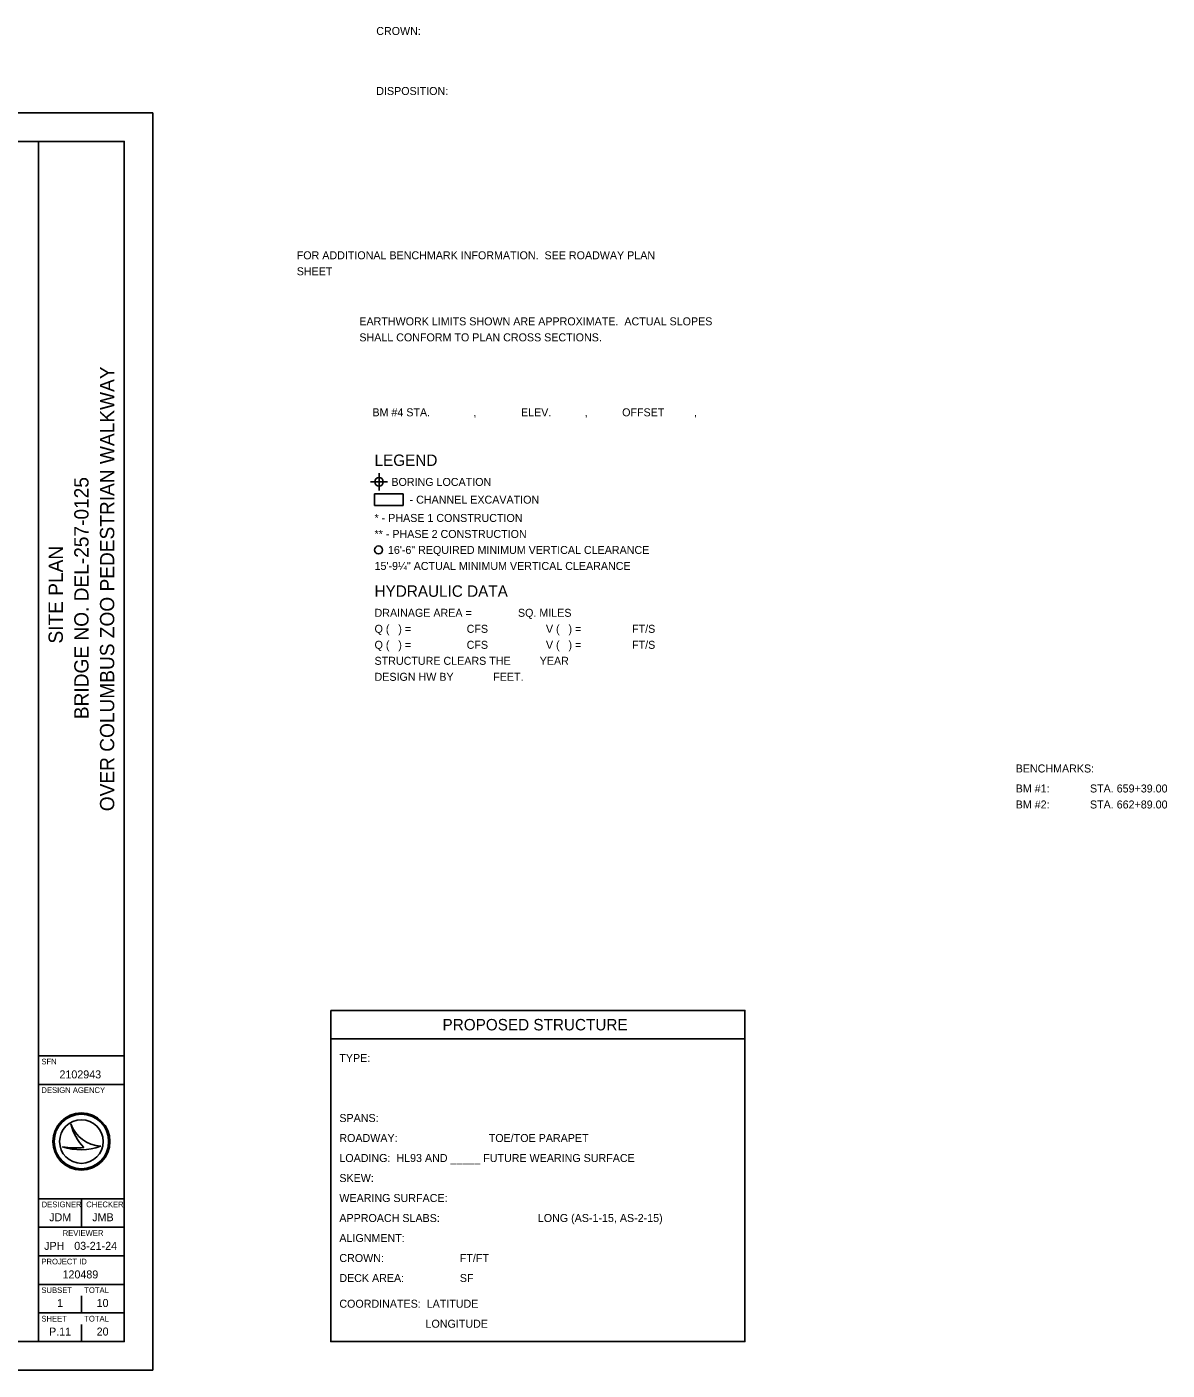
# Model space of a CAD drawing. Extents: x -8 to 51.8, y 0 to 37.2.
# Drawn here: x 31.8 to 51.75, y 0 to 23.51 of the extents above; entities that cross this region are included whole.
import ezdxf

# ---------------------------------------------------------------- set-up
doc = ezdxf.new("R2010")
doc.units = 0
for name, color, linetype in [('GT_Project_Soil_Boring', 7, 'Continuous'), ('SH_Border', 7, 'Continuous'), ('SH_Cut_Line', 7, 'Continuous'), ('SH_Data', 7, 'Continuous')]:
    doc.layers.add(name, color=color, linetype=linetype)

msp = doc.modelspace()

# ---------------------------------------------------------------- linework, layer by layer
at = {"layer": 'GT_Project_Soil_Boring'}
for p, q in [((37.959, 15.543), (37.809, 15.543)), ((37.959, 15.543), (37.884, 15.543)), ((37.959, 15.543), (37.959, 15.693)), ((37.959, 15.618), (37.959, 15.543)), ((37.959, 15.543), (37.959, 15.393)), ((37.959, 15.543), (38.109, 15.543)), ((37.959, 15.468), (37.959, 15.543)), ((37.959, 15.543), (38.034, 15.543))]:
    msp.add_line(p, q, dxfattribs=at)
msp.add_circle((37.959, 15.543), 0.075, dxfattribs=at)
for start, end in [(90, 180), (270, 360)]:
    msp.add_arc((37.959, 15.543), 0.075, start, end, dxfattribs=at)
at = {"layer": 'SH_Border'}
for p, q in [((32, 0.5), (32, 21.5)), ((32, 5.5), (33.5, 5.5)), ((32, 5), (33.5, 5)), ((32, 3), (33.5, 3)), ((32.75, 3), (32.75, 2.5)), ((32, 2.5), (33.5, 2.5)), ((32, 2), (33.5, 2)), ((32, 1.5), (33.5, 1.5)), ((32, 1), (33.5, 1))]:
    msp.add_line(p, q, dxfattribs=at)
msp.add_lwpolyline([(1.5, 21.5), (33.5, 21.5), (33.5, 0.5), (1.5, 0.5)], close=True, dxfattribs=at)
at = {"layer": 'SH_Cut_Line'}
msp.add_lwpolyline([(0, 0), (34, 0), (34, 22), (0, 22)], close=True, dxfattribs=at)
at = {"layer": 'SH_Data'}
for p, q in [((44.365, 5.795), (37.115, 5.795)), ((32.567, 4.31), (32.567, 4.31)), ((32.75, 4), (32.75, 4)), ((32.417, 3.91), (32.417, 3.91)), ((33.087, 3.919), (33.087, 3.919)), ((32.75, 1), (32.75, 1.3)), ((32.75, 0.5), (32.75, 0.8)), ((32.375, 0.675), (32.375, 0.675))]:
    msp.add_line(p, q, dxfattribs=at)
for points in [[(37.881, 15.332), (38.381, 15.332), (38.381, 15.132), (37.881, 15.132)], [(37.115, 6.295), (44.365, 6.295), (44.365, 0.5), (37.115, 0.5)]]:
    msp.add_lwpolyline(points, close=True, dxfattribs=at)
for centre, radius in [((37.951, 14.352), 0.07), ((32.75, 4), 0.5), ((32.75, 4), 0.477), ((32.75, 4), 0.477), ((32.75, 4), 0.382)]:
    msp.add_circle(centre, radius, dxfattribs=at)
for centre, radius, start, end in [((33.116, 4.498), 0.58, 198.9257, 198.9319), ((33.347, 4.47), 0.796, 191.6379, 191.6421), ((33.116, 4.498), 0.58, 198.9319, 267.1657), ((33.347, 4.47), 0.796, 191.6421, 226.0947), ((32.739, 4.87), 1.013, 251.4576, 290.0832), ((32.648, 5.154), 1.266, 259.4964, 259.4995), ((32.739, 4.87), 1.013, 251.4527, 251.4576), ((32.648, 5.154), 1.266, 259.4995, 276.6672)]:
    msp.add_arc(centre, radius, start, end, dxfattribs=at)

# ---------------------------------------------------------------- texts
for s, height, p in [('CROWN:', 0.14, (37.911, 23.363)), ('DISPOSITION:', 0.14, (37.911, 22.313)), ('FOR ADDITIONAL BENCHMARK INFORMATION.  SEE ROADWAY PLAN', 0.14, (36.519, 19.438)), ('SHEET      ', 0.14, (36.519, 19.158)), ('EARTHWORK LIMITS SHOWN ARE APPROXIMATE.  ACTUAL SLOPES', 0.14, (37.615, 18.282)), ('SHALL CONFORM TO PLAN CROSS SECTIONS.', 0.14, (37.615, 18.002)), ('BM #4 STA.', 0.14, (37.844, 16.69)), ('         ,', 0.14, (39.144, 16.69)), ('ELEV.', 0.14, (40.444, 16.69)), ('       ,', 0.14, (41.194, 16.69)), ('OFFSET', 0.14, (42.215, 16.69)), ('      ,', 0.14, (43.159, 16.69)), ('LEGEND', 0.2, (37.881, 15.822)), ('BORING LOCATION', 0.14, (38.176, 15.472)), ('- CHANNEL EXCAVATION', 0.14, (38.495, 15.162)), ('* - PHASE 1 CONSTRUCTION', 0.14, (37.881, 14.842)), ('** - PHASE 2 CONSTRUCTION', 0.14, (37.881, 14.562)), ('HYDRAULIC DATA', 0.2, (37.881, 13.532)), ('DRAINAGE AREA =', 0.14, (37.881, 13.182)), ('SQ. MILES', 0.14, (40.391, 13.182)), ('Q (   ) =', 0.14, (37.881, 12.902)), ('      CFS', 0.14, (39.181, 12.902)), ('V (   ) =', 0.14, (40.881, 12.902)), ('    FT/S', 0.14, (42.181, 12.902)), ('Q (   ) =', 0.14, (37.881, 12.622)), ('      CFS', 0.14, (39.181, 12.622)), ('V (   ) =', 0.14, (40.881, 12.622)), ('    FT/S', 0.14, (42.181, 12.622)), ('STRUCTURE CLEARS THE', 0.14, (37.881, 12.342)), ('YEAR', 0.14, (40.772, 12.342)), ('DESIGN HW BY', 0.14, (37.881, 12.062)), ('FEET.', 0.14, (39.958, 12.062)), ('BENCHMARKS:', 0.14, (49.103, 10.458)), ('BM #1:', 0.14, (49.103, 10.108)), ('STA. 659+39.00', 0.14, (50.403, 10.108)), ('BM #2:', 0.14, (49.103, 9.828)), ('STA. 662+89.00', 0.14, (50.403, 9.828)), ('PROPOSED STRUCTURE', 0.2, (39.071, 5.945)), ('SFN', 0.1, (32.05, 5.35)), ('TYPE:', 0.14, (37.265, 5.392)), ('2102943', 0.14, (32.366, 5.105)), ('DESIGN AGENCY', 0.1, (32.05, 4.85)), ('SPANS:', 0.14, (37.265, 4.342)), ('ROADWAY:', 0.14, (37.265, 3.992)), ('TOE/TOE PARAPET', 0.14, (39.88, 3.992)), ('LOADING:  HL93 AND _____ FUTURE WEARING SURFACE', 0.14, (37.265, 3.642)), ('SKEW:', 0.14, (37.265, 3.292)), ('WEARING SURFACE:', 0.14, (37.265, 2.942)), ('DESIGNER', 0.1, (32.054, 2.85)), ('CHECKER', 0.1, (32.835, 2.85)), ('JDM', 0.14, (32.187, 2.605)), ('JMB', 0.14, (32.94, 2.605)), ('APPROACH SLABS:', 0.14, (37.265, 2.592)), ('LONG (AS-1-15, AS-2-15)', 0.14, (40.739, 2.592)), ('REVIEWER', 0.1, (32.422, 2.35)), ('ALIGNMENT:', 0.14, (37.265, 2.242)), ('JPH', 0.14, (32.098, 2.105)), ('03-21-24', 0.14, (32.625, 2.105)), ('PROJECT ID', 0.1, (32.05, 1.85)), ('CROWN:', 0.14, (37.265, 1.892)), ('FT/FT', 0.14, (39.374, 1.892)), ('120489', 0.14, (32.42, 1.605)), ('DECK AREA:', 0.14, (37.265, 1.542)), ('SF', 0.14, (39.374, 1.542)), ('SUBSET', 0.1, (32.05, 1.35)), ('TOTAL', 0.1, (32.8, 1.35)), ('1', 0.14, (32.325, 1.105)), ('10', 0.14, (33.017, 1.105)), ('COORDINATES:  LATITUDE', 0.14, (37.265, 1.092)), ('SHEET', 0.1, (32.05, 0.85)), ('TOTAL', 0.1, (32.8, 0.85)), ('P.11', 0.14, (32.184, 0.605)), ('20', 0.14, (33.017, 0.605)), ('                             LONGITUDE', 0.14, (37.265, 0.742))]:
    msp.add_text(s, height=height, dxfattribs=at).set_placement(p)
for s, height, rotation, p in [('OVER COLUMBUS ZOO PEDESTRIAN WALKWAY', 0.25, 90, (33.325, 9.78)), ('BRIDGE NO. DEL-257-0125', 0.25, 90, (32.875, 11.391)), ('SITE PLAN', 0.25, 90, (32.425, 12.714)), ('16\'-6" REQUIRED MINIMUM VERTICAL CLEARANCE', 0.14, 0, (38.115, 14.282)), ('15\'-9¼" ACTUAL MINIMUM VERTICAL CLEARANCE', 0.14, 0, (37.881, 14.002))]:
    msp.add_text(s, height=height, rotation=rotation, dxfattribs=at).set_placement(p)

doc.saveas('drawing.dxf')
